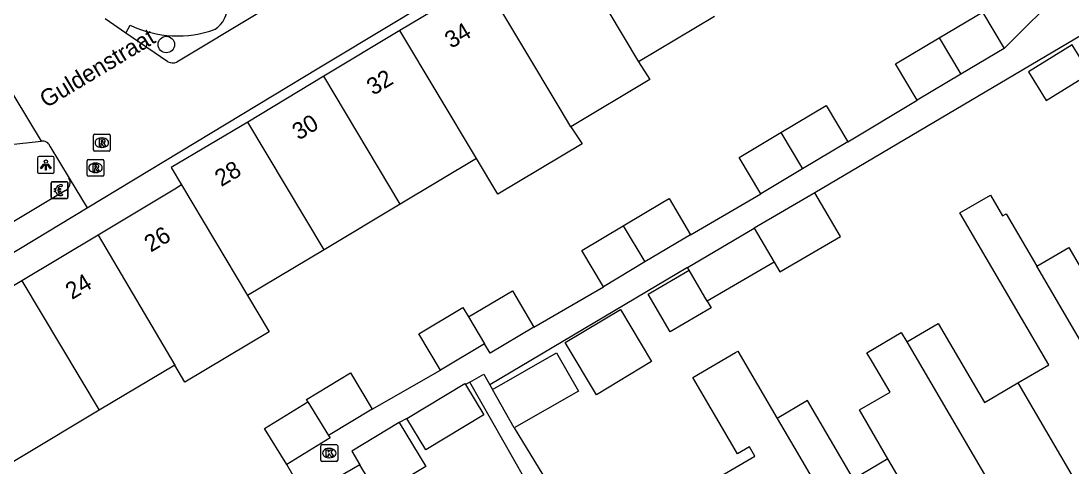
# Model space of a CAD drawing. Extents: x 161771 to 163125, y 382479 to 383177.
# Drawn here: x 162244.4 to 162306.6, y 382858.3 to 382884.8 of the extents above; entities that cross this region are included whole.
import ezdxf

# ---------------------------------------------------------------- set-up
doc = ezdxf.new("R2010")
doc.units = 0
for name, color, linetype in [('IMGEO_Betaalautomaat', 7, 'Continuous'), ('IMGEO_Boom', 7, 'Continuous'), ('IMGEO_Kolk', 7, 'Continuous'), ('IMGEO_Lichtpunt', 7, 'Continuous'), ('IMGEO_Openbare_ruimte_label', 7, 'Continuous'), ('IMGEO_Pand', 7, 'Continuous'), ('IMGEO_Pand_nummerreeks', 7, 'Continuous'), ('IMGEO_Parkeervlak_open', 7, 'Continuous'), ('IMGEO_Rioolput', 7, 'Continuous'), ('IMGEO_Voetpad_open', 7, 'Continuous'), ('IMGEO_Woonerf_open', 7, 'Continuous')]:
    doc.layers.add(name, color=color, linetype=linetype)

msp = doc.modelspace()

# ---------------------------------------------------------------- linework, layer by layer
at = {"layer": 'IMGEO_Betaalautomaat'}
for p, q in [((162246.186, 382874.311), (162246.186, 382875.152)), ((162246.186, 382875.152), (162246.186, 382874.311)), ((162246.261, 382875.235), (162247.102, 382875.235)), ((162247.102, 382875.235), (162246.261, 382875.235)), ((162246.848, 382875.04), (162246.831, 382874.94)), ((162247.185, 382875.161), (162247.185, 382874.32)), ((162247.185, 382874.32), (162247.185, 382875.161)), ((162246.469, 382874.699), (162246.469, 382874.767)), ((162246.59, 382874.767), (162246.59, 382874.699)), ((162246.835, 382874.534), (162246.857, 382874.447)), ((162247.111, 382874.236), (162246.27, 382874.236)), ((162246.27, 382874.236), (162247.111, 382874.236))]:
    msp.add_line(p, q, dxfattribs=at)
for points in [[(162246.469, 382874.767), (162246.4, 382874.767), (162246.4, 382874.836), (162246.479, 382874.836)], [(162246.474, 382874.63), (162246.4, 382874.63), (162246.4, 382874.699), (162246.469, 382874.699)], [(162246.601, 382874.836), (162246.748, 382874.836), (162246.748, 382874.767), (162246.59, 382874.767)], [(162246.59, 382874.699), (162246.748, 382874.699), (162246.748, 382874.63), (162246.604, 382874.63)]]:
    msp.add_lwpolyline(points, dxfattribs=at)
for centre, radius, start, end in [((162246.264, 382875.158), 0.0779, 92.4484, 184.28452), ((162246.264, 382875.158), 0.0779, 92.4484, 184.28452), ((162246.762, 382874.76), 0.293, 73.01398, 165.01395), ((162246.768, 382874.773), 0.179, 69.32359, 159.56827), ((162247.108, 382875.158), 0.0779, 2.4484, 94.28452), ((162247.108, 382875.158), 0.0779, 2.4484, 94.28452), ((162246.264, 382874.314), 0.0779, 182.4484, 274.28452), ((162246.264, 382874.314), 0.0779, 182.4484, 274.28452), ((162246.735, 382874.685), 0.267, 191.80956, 297.03891), ((162246.768, 382874.7), 0.179, 202.76249, 291.86925), ((162247.108, 382874.314), 0.0779, 272.4484, 4.28452), ((162247.108, 382874.314), 0.0779, 272.4484, 4.28452)]:
    msp.add_arc(centre, radius, start, end, dxfattribs=at)
at = {"layer": 'IMGEO_Boom'}
msp.add_circle((162253.017, 382883.36), 0.489, dxfattribs=at)
at = {"layer": 'IMGEO_Kolk'}
for p, q in [((162262.17, 382858.733), (162262.17, 382859.585)), ((162262.245, 382859.659), (162263.097, 382859.659)), ((162262.658, 382859.439), (162262.683, 382859.439)), ((162263.171, 382859.585), (162263.171, 382858.733)), ((162262.681, 382858.879), (162262.656, 382858.879)), ((162263.097, 382858.659), (162262.245, 382858.659))]:
    msp.add_line(p, q, dxfattribs=at)
for points in [[(162262.17, 382858.733), (162262.17, 382859.585)], [(162262.245, 382859.659), (162263.097, 382859.659)], [(162262.491, 382859.359), (162262.614, 382859.359), (162262.614, 382859.208), (162262.744, 382859.359), (162262.908, 382859.359), (162262.762, 382859.208), (162262.915, 382858.959), (162262.763, 382858.959), (162262.678, 382859.123), (162262.614, 382859.056), (162262.614, 382858.959), (162262.491, 382858.959), (162262.491, 382859.359)], [(162263.171, 382859.585), (162263.171, 382858.733)], [(162263.097, 382858.659), (162262.245, 382858.659)]]:
    msp.add_lwpolyline(points, dxfattribs=at)
for centre, start, end in [((162262.247, 382859.583), 91.55205, 178.44795), ((162262.247, 382859.583), 91.55205, 178.44795), ((162263.095, 382859.583), 1.55205, 88.44795), ((162263.095, 382859.583), 1.55205, 88.44795), ((162262.247, 382858.735), 181.55205, 268.44795), ((162262.247, 382858.735), 181.55205, 268.44795), ((162263.095, 382858.735), 271.55205, 358.44795), ((162263.095, 382858.735), 271.55205, 358.44795)]:
    msp.add_arc(centre, 0.0765, start, end, dxfattribs=at)
for centre, major_axis, ratio, start_param, end_param in [((162262.657, 382859.159), (-0.387, 0.002), 0.722429, 4.712389, 7.853982), ((162262.682, 382859.159), (-0.39, 0.002), 0.717154, 1.570796, 4.712389)]:
    msp.add_ellipse(centre, major_axis=major_axis, ratio=ratio, start_param=start_param, end_param=end_param, dxfattribs=at)
at = {"layer": 'IMGEO_Lichtpunt'}
for p, q in [((162245.38, 382876.632), (162245.38, 382875.825)), ((162245.38, 382876.632), (162245.38, 382875.825)), ((162246.282, 382876.727), (162245.474, 382876.727)), ((162246.282, 382876.727), (162245.474, 382876.727)), ((162246.376, 382875.825), (162246.376, 382876.632)), ((162246.376, 382875.825), (162246.376, 382876.632)), ((162245.474, 382875.731), (162246.282, 382875.731)), ((162245.474, 382875.731), (162246.282, 382875.731))]:
    msp.add_line(p, q, dxfattribs=at)
for points in [[(162245.754, 382876.296), (162245.793, 382876.268), (162245.605, 382876.006), (162245.567, 382876.033), (162245.754, 382876.296)], [(162245.856, 382876.248), (162245.903, 382876.248), (162245.903, 382875.926), (162245.856, 382875.926), (162245.856, 382876.248)], [(162245.966, 382876.268), (162246.004, 382876.295), (162246.191, 382876.033), (162246.152, 382876.005), (162245.966, 382876.268)]]:
    msp.add_lwpolyline(points, dxfattribs=at)
msp.add_circle((162245.879, 382876.43), 0.0994, dxfattribs=at)
for centre, start, end in [((162245.474, 382876.632), 90, 180), ((162245.474, 382876.632), 90, 180), ((162246.282, 382876.632), 0, 90), ((162246.282, 382876.632), 0, 90), ((162245.474, 382875.825), 180, 270), ((162245.474, 382875.825), 180, 270), ((162246.282, 382875.825), 270, 0), ((162246.282, 382875.825), 270, 360)]:
    msp.add_arc(centre, 0.0946, start, end, dxfattribs=at)
at = {"layer": 'IMGEO_Pand'}
for points in [[(162276.448, 382889.947), (162281.001, 382882.337)], [(162271.804, 382887.157), (162266.86, 382884.187)], [(162276.987, 382878.494), (162276.349, 382879.559), (162271.804, 382887.157)], [(162285.499, 382885.022), (162281.001, 382882.337)], [(162298.818, 382883.756), (162301.386, 382885.283), (162302.664, 382883.134)], [(162266.86, 382884.187), (162262.352, 382881.479)], [(162271.398, 382876.603), (162266.86, 382884.187)], [(162297.503, 382880.065), (162296.225, 382882.214), (162298.818, 382883.756)], [(162298.818, 382883.756), (162300.1, 382881.609)], [(162302.664, 382883.134), (162300.1, 382881.609)], [(162305.157, 382880.053), (162307.739, 382881.654), (162306.688, 382883.35), (162304.106, 382881.748), (162305.157, 382880.053)], [(162281.001, 382882.337), (162281.673, 382881.295), (162276.987, 382878.494)], [(162262.352, 382881.479), (162257.837, 382878.767)], [(162266.883, 382873.907), (162262.352, 382881.479)], [(162300.1, 382881.609), (162297.503, 382880.065)], [(162289.425, 382878.14), (162292.118, 382879.743), (162293.397, 382877.595)], [(162257.837, 382878.767), (162253.312, 382876.074), (162253.925, 382875.044)], [(162262.361, 382871.206), (162257.837, 382878.767)], [(162276.987, 382878.494), (162277.661, 382877.486), (162272.654, 382874.5), (162271.398, 382876.603)], [(162288.236, 382874.523), (162286.957, 382876.671), (162289.425, 382878.14)], [(162289.425, 382878.14), (162290.706, 382875.993)], [(162293.397, 382877.595), (162290.706, 382875.993)], [(162271.398, 382876.603), (162266.883, 382873.907)], [(162290.706, 382875.993), (162288.236, 382874.523)], [(162253.925, 382875.044), (162253.519, 382874.8), (162251.245, 382873.435), (162248.972, 382872.07)], [(162253.925, 382875.044), (162257.821, 382868.496)], [(162291.445, 382874.578), (162287.859, 382872.477)], [(162289.032, 382870.476), (162289.376, 382869.888), (162292.962, 382871.989), (162291.445, 382874.578)], [(162303.471, 382863.322), (162305.301, 382864.394), (162301.124, 382871.526), (162300.037, 382873.382), (162301.853, 382874.446), (162302.573, 382873.217), (162302.772, 382873.333), (162304.593, 382870.224)], [(162266.883, 382873.907), (162262.361, 382871.206)], [(162280.096, 382872.629), (162282.447, 382874.03), (162282.805, 382874.237), (162284.082, 382872.088)], [(162278.918, 382869.017), (162277.64, 382871.166), (162280.096, 382872.629)], [(162280.096, 382872.629), (162281.379, 382870.48)], [(162283.896, 382870.155), (162287.859, 382872.477)], [(162287.859, 382872.477), (162289.032, 382870.476)], [(162248.972, 382872.07), (162244.449, 382869.355)], [(162248.972, 382872.07), (162253.512, 382864.374)], [(162284.082, 382872.088), (162281.379, 382870.48)], [(162262.361, 382871.206), (162257.821, 382868.496)], [(162304.593, 382870.224), (162306.491, 382871.335), (162309.214, 382866.685), (162311.162, 382867.826)], [(162281.379, 382870.48), (162278.918, 382869.017)], [(162285.069, 382868.154), (162285.298, 382867.762), (162282.872, 382866.34), (162281.564, 382868.572), (162283.991, 382869.994)], [(162283.991, 382869.994), (162283.896, 382870.155)], [(162285.069, 382868.154), (162283.991, 382869.994)], [(162289.032, 382870.476), (162285.069, 382868.154)], [(162311.491, 382858.449), (162304.593, 382870.224)], [(162244.449, 382869.355), (162239.66, 382866.479)], [(162244.449, 382869.355), (162249.033, 382861.693)], [(162270.926, 382867.232), (162273.523, 382868.773), (162274.799, 382866.623)], [(162257.821, 382868.496), (162259.108, 382866.333), (162254.113, 382863.36), (162253.512, 382864.374)], [(162269.268, 382864.076), (162267.979, 382866.218), (162270.588, 382867.789), (162270.926, 382867.232)], [(162281.775, 382864.586), (162278.499, 382862.62), (162276.646, 382865.708), (162279.922, 382867.674), (162281.775, 382864.586)], [(162270.926, 382867.232), (162271.866, 382865.64)], [(162296.887, 382865.741), (162298.757, 382866.836), (162301.494, 382862.164), (162303.471, 382863.322)], [(162274.799, 382866.623), (162272.197, 382865.079), (162271.866, 382865.64)], [(162295.776, 382858.822), (162294.083, 382861.712), (162295.9, 382862.777), (162294.859, 382864.553), (162294.535, 382865.106), (162296.563, 382866.294), (162296.887, 382865.741)], [(162271.866, 382865.64), (162269.268, 382864.076)], [(162296.887, 382865.741), (162303.801, 382853.94)], [(162272.341, 382862.932), (162276.139, 382865.104), (162277.436, 382862.837), (162273.638, 382860.664)], [(162285.998, 382857.875), (162287.89, 382858.983), (162287.571, 382859.528), (162286.869, 382859.117), (162284.221, 382863.64), (162286.744, 382865.117), (162286.876, 382865.194), (162289.206, 382861.217)], [(162253.512, 382864.374), (162249.033, 382861.693)], [(162261.401, 382862.189), (162261.314, 382862.331), (162263.926, 382863.908), (162265.218, 382861.769)], [(162267.263, 382861.207), (162270.707, 382863.285), (162270.75, 382863.214)], [(162270.75, 382863.214), (162271.831, 382861.422), (162268.387, 382859.344), (162267.263, 382861.207)], [(162303.471, 382863.322), (162307.646, 382856.195)], [(162273.638, 382860.664), (162272.341, 382862.932)], [(162260.151, 382858.489), (162258.844, 382860.62), (162261.401, 382862.189)], [(162261.401, 382862.189), (162262.634, 382860.207)], [(162295.776, 382858.822), (162293.732, 382857.624), (162291.009, 382862.273), (162289.206, 382861.217)], [(162249.033, 382861.693), (162244.335, 382858.88), (162238.836, 382855.588), (162237.48, 382857.838)], [(162265.218, 382861.769), (162262.634, 382860.207)], [(162289.206, 382861.217), (162290.193, 382859.532), (162296.112, 382849.431)], [(162266.816, 382860.977), (162264.001, 382859.278), (162264.493, 382858.463)], [(162266.816, 382860.977), (162268.392, 382858.365), (162265.577, 382856.666), (162264.493, 382858.463)], [(162262.634, 382860.207), (162262.721, 382860.065), (162260.151, 382858.489)], [(162299.957, 382851.686), (162295.776, 382858.822)]]:
    msp.add_lwpolyline(points, dxfattribs=at)
at = {"layer": 'IMGEO_Parkeervlak_open'}
for points in [[(162237.54, 382890.991), (162245.599, 382877.627)], [(162235.47, 382883.657), (162239.477, 382876.957), (162245.599, 382877.627)]]:
    msp.add_lwpolyline(points, dxfattribs=at)
at = {"layer": 'IMGEO_Rioolput'}
for p, q in [((162248.769, 382878.046), (162249.621, 382878.046)), ((162248.694, 382877.12), (162248.694, 382877.972)), ((162249.182, 382877.826), (162249.207, 382877.826)), ((162249.695, 382877.972), (162249.695, 382877.12)), ((162249.621, 382877.046), (162248.769, 382877.046)), ((162249.205, 382877.266), (162249.18, 382877.266)), ((162248.321, 382875.628), (162248.321, 382876.48)), ((162248.396, 382876.554), (162249.248, 382876.554)), ((162248.809, 382876.334), (162248.834, 382876.334)), ((162249.322, 382876.48), (162249.322, 382875.628)), ((162249.248, 382875.554), (162248.396, 382875.554)), ((162248.832, 382875.774), (162248.807, 382875.774))]:
    msp.add_line(p, q, dxfattribs=at)
for points in [[(162248.769, 382878.046), (162249.621, 382878.046)], [(162248.694, 382877.12), (162248.694, 382877.972)], [(162249.283, 382877.744), (162249.031, 382877.746), (162249.031, 382877.346)], [(162249.031, 382877.346), (162249.155, 382877.346), (162249.155, 382877.508), (162249.166, 382877.508)], [(162249.209, 382877.665), (162249.155, 382877.665), (162249.155, 382877.584)], [(162249.155, 382877.584), (162249.207, 382877.584)], [(162249.213, 382877.479), (162249.284, 382877.346), (162249.424, 382877.346), (162249.359, 382877.472)], [(162249.695, 382877.972), (162249.695, 382877.12)], [(162249.621, 382877.046), (162248.769, 382877.046)], [(162248.321, 382875.628), (162248.321, 382876.48)], [(162248.396, 382876.554), (162249.248, 382876.554)], [(162248.91, 382876.252), (162248.658, 382876.254), (162248.658, 382875.854)], [(162248.836, 382876.173), (162248.782, 382876.173), (162248.782, 382876.092)], [(162249.322, 382876.48), (162249.322, 382875.628)], [(162249.248, 382875.554), (162248.396, 382875.554)], [(162248.658, 382875.854), (162248.782, 382875.854), (162248.782, 382876.016), (162248.793, 382876.016)], [(162248.782, 382876.092), (162248.834, 382876.092)], [(162248.84, 382875.987), (162248.911, 382875.854), (162249.051, 382875.854), (162248.986, 382875.98)]]:
    msp.add_lwpolyline(points, dxfattribs=at)
for centre, radius, start, end in [((162248.771, 382877.97), 0.0765, 91.55205, 178.44795), ((162248.771, 382877.97), 0.0765, 91.55205, 178.44795), ((162249.619, 382877.97), 0.0765, 1.55205, 88.44795), ((162249.619, 382877.97), 0.0765, 1.55205, 88.44795), ((162249.165, 382877.455), 0.0533, 26.02933, 88.69889), ((162249.191, 382877.773), 0.19, 274.7715, 282.96867), ((162249.215, 382877.569), 0.0964, 77.00612, 93.18647), ((162249.229, 382877.626), 0.0378, 276.66336, 79.67722), ((162249.282, 382877.634), 0.109, 350.36119, 89.41601), ((162249.28, 382877.634), 0.112, 277.58423, 350.98172), ((162249.264, 382877.419), 0.108, 29.51342, 73.79051), ((162248.771, 382877.122), 0.0765, 181.55205, 268.44795), ((162248.771, 382877.122), 0.0765, 181.55205, 268.44795), ((162249.619, 382877.122), 0.0765, 271.55205, 358.44795), ((162249.619, 382877.122), 0.0765, 271.55205, 358.44795), ((162248.398, 382876.478), 0.0765, 91.55205, 178.44795), ((162248.398, 382876.478), 0.0765, 91.55205, 178.44795), ((162248.842, 382876.077), 0.0964, 77.00612, 93.18647), ((162248.856, 382876.134), 0.0378, 276.66336, 79.67722), ((162248.909, 382876.142), 0.109, 350.36119, 89.41601), ((162248.907, 382876.142), 0.112, 277.58423, 350.98172), ((162249.246, 382876.478), 0.0765, 1.55205, 88.44795), ((162249.246, 382876.478), 0.0765, 1.55205, 88.44795), ((162248.398, 382875.63), 0.0765, 181.55205, 268.44795), ((162248.398, 382875.63), 0.0765, 181.55205, 268.44795), ((162248.792, 382875.963), 0.0533, 26.02933, 88.69889), ((162248.818, 382876.281), 0.19, 274.7715, 282.96867), ((162248.891, 382875.927), 0.108, 29.51342, 73.79051), ((162249.246, 382875.63), 0.0765, 271.55205, 358.44795), ((162249.246, 382875.63), 0.0765, 271.55205, 358.44795)]:
    msp.add_arc(centre, radius, start, end, dxfattribs=at)
for centre, major_axis, ratio, start_param, end_param in [((162249.181, 382877.546), (-0.387, 0.002), 0.722429, 4.712389, 7.853982), ((162249.206, 382877.546), (-0.39, 0.002), 0.717154, 1.570796, 4.712389), ((162248.808, 382876.054), (-0.387, 0.002), 0.722429, 4.712389, 7.853982), ((162248.833, 382876.054), (-0.39, 0.002), 0.717154, 1.570796, 4.712389)]:
    msp.add_ellipse(centre, major_axis=major_axis, ratio=ratio, start_param=start_param, end_param=end_param, dxfattribs=at)
at = {"layer": 'IMGEO_Voetpad_open'}
for points in [[(162211.555, 382915.58), (162212.177, 382915.93), (162232.727, 382881.7), (162233.779, 382879.947), (162240.406, 382868.9), (162248.32, 382873.678)], [(162302.664, 382883.134), (162306.196, 382886.659)], [(162250.618, 382884.043), (162249.393, 382884.874)], [(162250.618, 382884.043), (162250.883, 382884.512)], [(162307.715, 382884.189), (162291.445, 382874.578)], [(162293.397, 382877.595), (162297.503, 382880.065)], [(162247.25, 382875.451), (162248.32, 382873.678)], [(162247.049, 382874.709), (162241.193, 382871.219)], [(162284.082, 382872.088), (162288.236, 382874.523)], [(162283.896, 382870.155), (162272.18, 382863.212)], [(162274.799, 382866.623), (162278.918, 382869.017)], [(162265.218, 382861.769), (162269.268, 382864.076)], [(162271.009, 382863.362), (162271.824, 382863.83), (162272.18, 382863.212)], [(162271.009, 382863.362), (162270.75, 382863.214)], [(162275.563, 382855.346), (162271.009, 382863.362)], [(162272.18, 382863.212), (162272.341, 382862.932)], [(162267.263, 382861.207), (162266.816, 382860.977)], [(162273.638, 382860.664), (162277.514, 382854.28)], [(162256.392, 382855.375), (162260.537, 382857.839), (162260.151, 382858.489)], [(162264.493, 382858.463), (162263.223, 382857.735)]]:
    msp.add_lwpolyline(points, dxfattribs=at)
for centre, radius, start, end in [((162254.947, 382885.686), 1.712, 303.89648, 0.96819), ((162253.683, 382890.301), 6.431, 244.18455, 290.1806), ((162246.771, 382875.183), 0.549, 300.41972, 29.26615)]:
    msp.add_arc(centre, radius, start, end, dxfattribs=at)
at = {"layer": 'IMGEO_Woonerf_open'}
for points in [[(162248.32, 382873.678), (162262.058, 382881.971), (162266.56, 382884.689), (162303.877, 382907.217)], [(162258.538, 382885.255), (162253.631, 382882.323)], [(162253.109, 382882.343), (162250.618, 382884.043)], [(162246.123, 382877.332), (162247.25, 382875.451)]]:
    msp.add_lwpolyline(points, dxfattribs=at)
for centre, radius, start, end in [((162253.392, 382882.913), 0.637, 243.58867, 292.023), ((162245.706, 382877.204), 0.437, 17.10457, 104.1384)]:
    msp.add_arc(centre, radius, start, end, dxfattribs=at)

# ---------------------------------------------------------------- texts
at = {"layer": 'IMGEO_Openbare_ruimte_label'}
msp.add_text('Guldenstraat', height=1, rotation=31.00307, dxfattribs=at).set_placement((162245.899, 382879.576))
at = {"layer": 'IMGEO_Pand_nummerreeks'}
for s, rotation, p in [('34', 30.99349, (162269.9, 382883.097)), ('32', 30.99349, (162265.276, 382880.319)), ('30', 30.99349, (162260.857, 382877.664)), ('28', 30.54438, (162256.268, 382874.913)), ('26', 30.97983, (162252.094, 382871.028)), ('24', 30.97983, (162247.423, 382868.224))]:
    msp.add_text(s, height=1, rotation=rotation, dxfattribs=at).set_placement(p)

doc.saveas('drawing.dxf')
